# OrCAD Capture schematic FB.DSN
size C
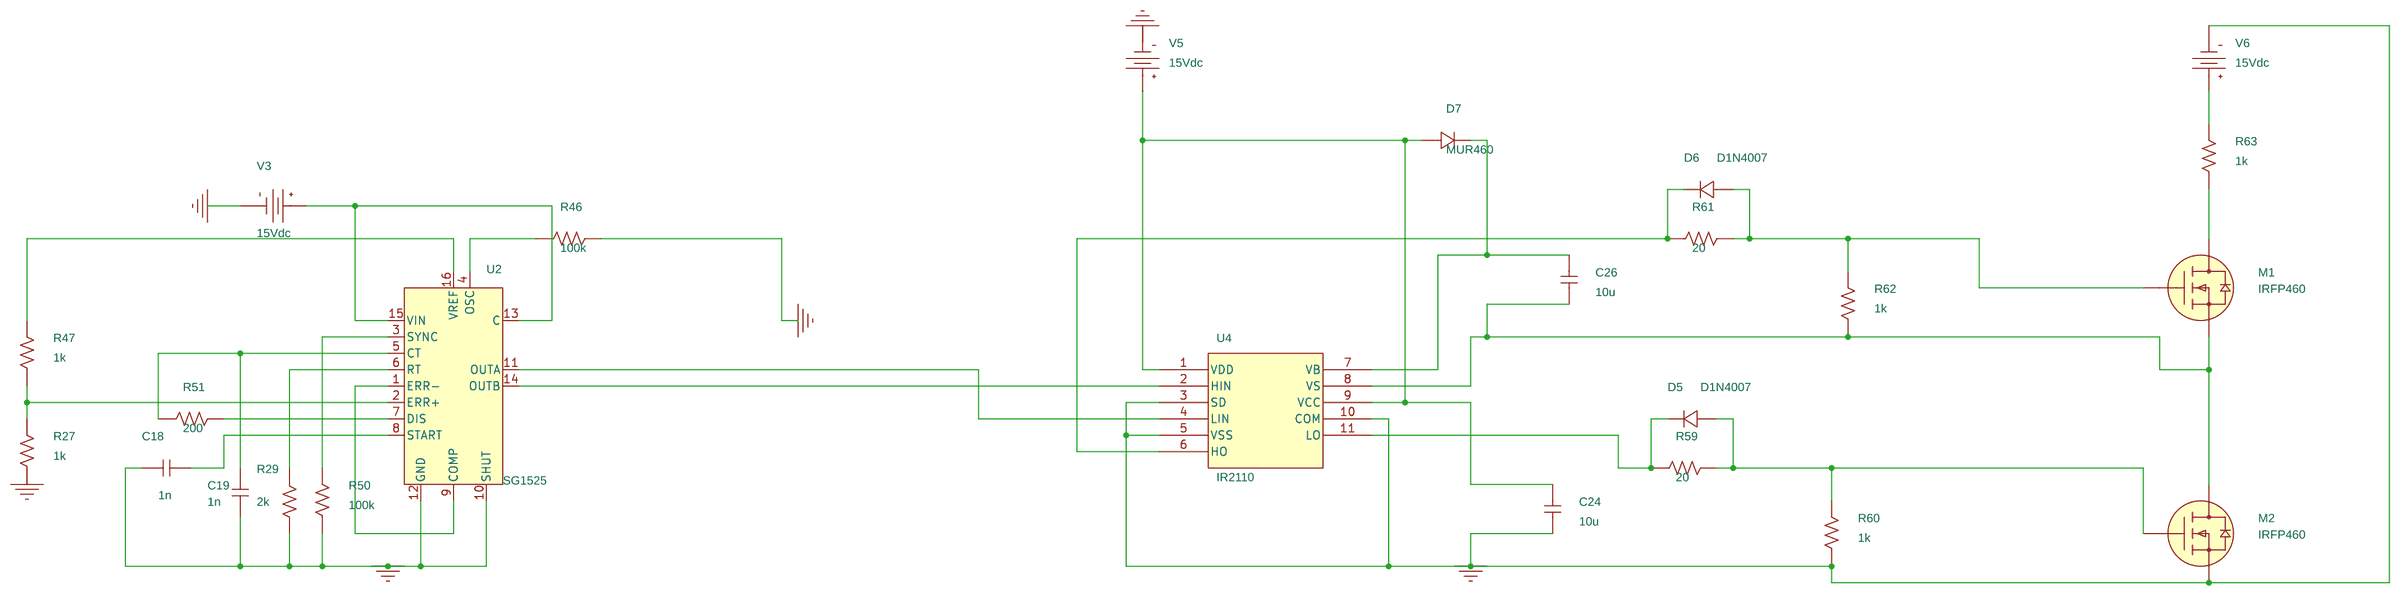
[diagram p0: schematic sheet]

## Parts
C18  1n  [RAD/CK05]
C19  1n  [RAD/CK05]
C24  10u  [RAD/CK05]
C26  10u  [RAD/CK05]
D5  D1N4007  [DO-41]
D6  D1N4007  [DO-41]
D7  MUR460  [DO-27]
M1  IRFP460  [TO247AC]
M2  IRFP460  [TO247AC]
R27  1k  [AX/RC05]
R29  2k  [AX/RC05]
R46  100k  [AX/RC05]
R47  1k  [AX/RC05]
R50  100k  [AX/RC05]
R51  200  [AX/RC05]
R59  20  [AX/RC05]
R60  1k  [AX/RC05]
R61  20  [AX/RC05]
R62  1k  [AX/RC05]
R63  1k  [AX/RC05]
U2  SG1525  [DIP.100/16/W.300/L.900]
U4  IR2110
V3  VDC
V5  VDC
V6  VDC

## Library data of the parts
C18 C19 C24 C26 = C
D5 D6 = D1N4007
D7 = MUR460
M1 M2 = IRFP460
R27 R29 R46 R47 R50 R51 R59-R63 = R
U2 = SG1525: DEADTIME: 1us; PERIOD: 20us
U4 = IR2110
V3 V5 V6 = VDC: DC: 15Vdc

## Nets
0: C18.2 C19.2 C24.1 M2.3(S) R27.1 R29.2 R46.2 R50.1 R60.1 U2.10(SHUT) U2.12(GND) U4.3(SD) U4.5(VSS) U4.10(COM) V3.1(-) V5.1(-) V6.1(-)
N25945: U2.1(ERR-) U2.9(COMP)
N25953: R47.2 U2.16(VREF)
N25993: R46.1 U2.4(OSC)
N26001: U2.13(C) U2.15(VIN) V3.0(+)
N26089: R27.2 R47.1 U2.2(ERR+)
N26117: R29.1 U2.6(RT)
N26177: C19.1 R51.1 U2.5(CT)
N26241: C18.1 U2.8(START)
N26301: R50.2 U2.3(SYNC)
N26349: R51.2 U2.7(DIS)
N27056: U2.11(OUTA) U4.4(LIN)
N30740: C24.2 D7.2 U4.1(VDD) U4.9(VCC) V5.0(+)
N30764: D5.2 R59.1 U4.11(LO)
N30772: D5.1 M2.2(G) R59.2 R60.2
N30852: C26.2 D7.1 U4.7(VB)
N30872: C26.1 M1.3(S) M2.1(D) R62.1 U4.8(VS)
N30892: D6.2 R61.1 U4.6(HO)
N30900: D6.1 M1.2(G) R61.2 R62.2
N32139: U2.14(OUTB) U4.2(HIN)
N32628: R63.2 V6.0(+)
N32632: M1.1(D) R63.1
